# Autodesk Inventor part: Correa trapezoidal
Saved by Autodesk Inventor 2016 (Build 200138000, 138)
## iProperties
Created: 2016-06
Part Number: Correa trapezoidal
Material: Rubber
Document SubType Name: Modeling
Designer: adm
Mass: 49.1524 g
Surface Area: 249.911 cm^2
Volume: 52.8521 cm^3
Density: 0.93 g/cm^3
Appearance: Rubber - Black - Version 1.1
CustomPartVersion: 1
Author: adm
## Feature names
1. Correa
## Parameters: da_Alfa = 40 deg, da_H = 7.9375 mm, da_Bw = 10.6172 mm, da_Hw = 2.6822 mm, d0 = 10.6172 mm, d1 = 2.6822 mm, d2 = 40 deg, d3 = 7.9375 mm, d4 = 0, d5 = 0, d6 = 0, d7 = 0, d8 = 0, d9 = 0
